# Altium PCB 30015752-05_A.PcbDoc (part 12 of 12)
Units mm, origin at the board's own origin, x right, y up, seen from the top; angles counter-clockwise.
Board outline 100.05 x 72 mm, 10 copper layers (Top, GND_2, Signal_3, Signal_4, PWR_5, GND_6, Signal_7, Signal_8, GND_9, Bottom), stack 1.493 mm thick; 577 components, 546 nets, 2389 pads, 1412 vias.
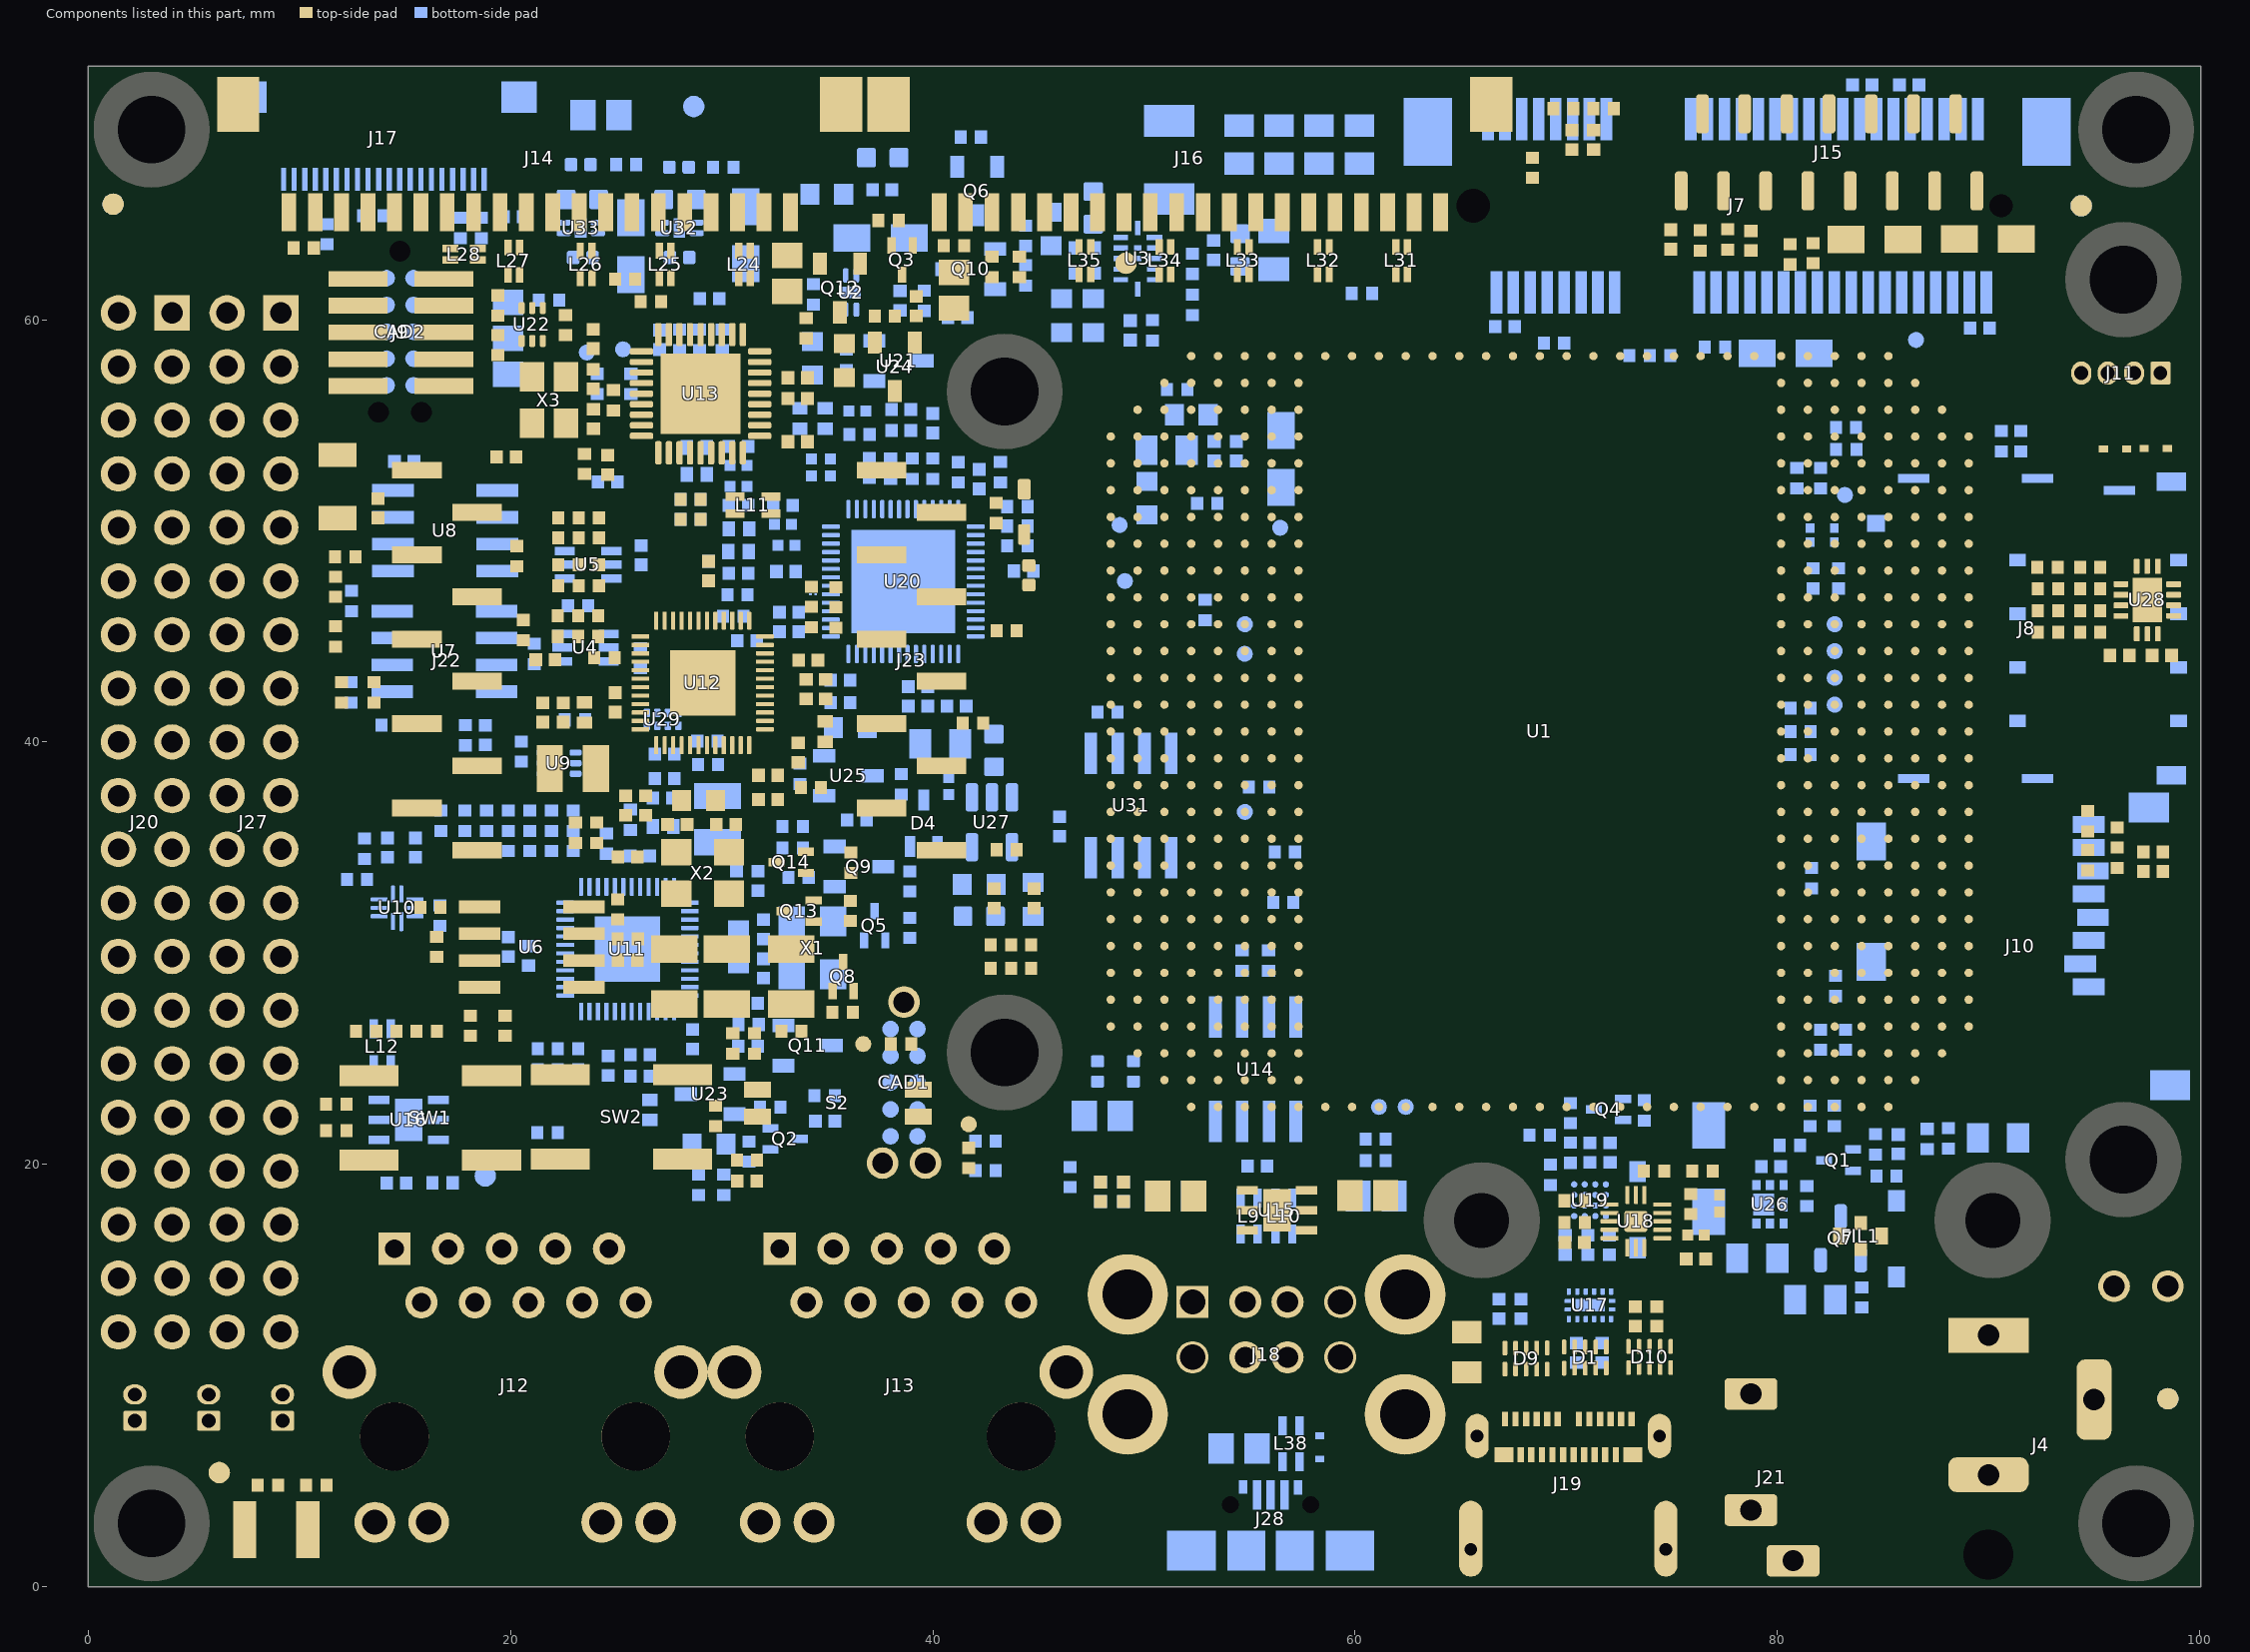
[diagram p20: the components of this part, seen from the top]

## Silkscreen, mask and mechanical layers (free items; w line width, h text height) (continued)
Sheet Graphics:
  drawing of 795 lines, arcs and shapes, not listed
  text "1" at 333.273,124.993 h4.57
  text "4" at -85.192,124.358 h4.57
  text "3" at 57.048,124.358 h4.57
  text "2" at 196.113,123.723 h4.57
  text "D" at -145.517,85.623 h7.11
  text "D" at 399.821,81.178 h7.11
  text "CUT OUT" at 45.695,72.644 h1.25
  text "CUT OUT" at 1.27,72.593 h1.25
  text "CUT OUT" at 153.492,72.593 h1.25
  text "CUT OUT" at 254.356,72.593 h1.25
  text "CUT OUT" at 101.981,63.754 h1.25 r90
  text "CUT OUT" at 204.394,63.703 h1.25 r90
  text "CUT OUT" at 306.908,63.043 h1.25 r90
  text "CUT OUT" at 71,39.5 h1.5
  text "CUT OUT" at 204.445,31.521 h1.25 r90
  text "CUT OUT" at -0.66,30.734 h1.25 r90
  text "CUT OUT" at 306.934,28.245 h1.25 r90
  text "CUT OUT" at 101.981,27.584 h1.25 r90
  text "CUT OUT" at 25.248,-2.616 h1.5
  text "CUT OUT" at 107.823,-2.718 h1.5
  text "CUT OUT" at 213.639,-2.896 h1.5
  text "CUT OUT" at 286.233,-2.896 h1.5
  text "C" at -145.517,-23.597 h7.11
  text "C" at 398.551,-23.597 h7.11
  text "1. Manufacture in accordance with IPC-6012, class 2. Inspect to IPC-A-600, class 2." at 185,-30 h6
  text "T" at -119.157,-40.532 h6.06
  text "a" at -116.729,-40.532 h6.06
  text "r" at -114.3,-40.532 h6.06
  text "g" at -112.565,-40.532 h6.06
  text "e" at -110.137,-40.532 h6.06
  text "t" at -107.361,-40.532 h6.06
  text "T" at -95.04,-40.532 h6.06
  text "o" at -92.611,-40.532 h6.06
  text "l" at -89.836,-40.532 h6.06
  text "+" at -87.407,-40.532 h6.06
  text "/" at -84.978,-40.532 h6.06
  text "-" at -82.897,-40.532 h6.06
  text "%" at -81.162,-40.532 h6.06
  text "L" at -72.696,-40.532 h6.06
  text "a" at -70.614,-40.532 h6.06
  text "y" at -68.186,-40.532 h6.06
  text "e" at -65.757,-40.532 h6.06
  text "r" at -62.981,-40.532 h6.06
  text "N" at -60.206,-40.532 h6.06
  text "o" at -56.736,-40.532 h6.06
  text "." at -53.961,-40.532 h6.06
  text "R" at -46.806,-40.532 h6.06
  text "e" at -44.03,-40.532 h6.06
  text "f" at -41.254,-40.532 h6.06
  text "e" at -39.519,-40.532 h6.06
  text "r" at -36.744,-40.532 h6.06
  text "e" at -35.009,-40.532 h6.06
  text "n" at -32.233,-40.532 h6.06
  text "c" at -29.458,-40.532 h6.06
  text "e" at -27.376,-40.532 h6.06
  text "T" at -20.915,-40.532 h6.06
  text "r" at -18.486,-40.532 h6.06
  text "a" at -16.751,-40.532 h6.06
  text "c" at -14.323,-40.532 h6.06
  text "e" at -12.241,-40.532 h6.06
  text "S" at -8.425,-40.532 h6.06
  text "p" at -5.996,-40.532 h6.06
  text "a" at -3.22,-40.532 h6.06
  text "c" at -0.792,-40.532 h6.06
  text "i" at 1.29,-40.532 h6.06
  text "n" at 2.678,-40.532 h6.06
  text "g" at 5.454,-40.532 h6.06
  text "S" at 8.923,-40.532 h6.06
  text "1" at 11.352,-40.532 h6.06
  text "T" at 17.389,-40.532 h6.06
  text "r" at 19.818,-40.532 h6.06
  text "a" at 21.552,-40.532 h6.06
  text "c" at 23.981,-40.532 h6.06
  text "e" at 26.063,-40.532 h6.06
  text "W" at 29.879,-40.532 h6.06
  text "i" at 34.737,-40.532 h6.06
  text "d" at 36.124,-40.532 h6.06
  text "t" at 38.9,-40.532 h6.06
  text "h" at 40.635,-40.532 h6.06
  text "W" at 44.451,-40.532 h6.06
  text "1" at 49.309,-40.532 h6.06
  text "2. Manufacturing process and materials used must comply with ROHS directive / 2002/95/EC." at 185,-45 h6
  text "I" at -124.477,-47.471 h6.06
  text "m" at -123.09,-47.471 h6.06
  text "p" at -118.926,-47.471 h6.06
  text "e" at -116.15,-47.471 h6.06
  text "d" at -113.375,-47.471 h6.06
  text "a" at -110.599,-47.471 h6.06
  text "n" at -108.171,-47.471 h6.06
  text "c" at -105.395,-47.471 h6.06
  text "e" at -103.313,-47.471 h6.06
  text "L" at -43.968,-47.471 h6.06
  text "a" at -41.886,-47.471 h6.06
  text "y" at -39.458,-47.471 h6.06
  text "e" at -37.029,-47.471 h6.06
  text "r" at -34.254,-47.471 h6.06
  text "(" at -32.519,-47.471 h6.06
  text "s" at -30.784,-47.471 h6.06
  text ")" at -28.702,-47.471 h6.06
  text "(" at -8.856,-47.471 h6.06
  text "M" at -7.122,-47.471 h6.06
  text "I" at -2.611,-47.471 h6.06
  text "L" at -1.223,-47.471 h6.06
  text ")" at 0.858,-47.471 h6.06
  text "(" at 29.093,-47.471 h6.06
  text "M" at 30.828,-47.471 h6.06
  text "I" at 35.338,-47.471 h6.06
  text "L" at 36.726,-47.471 h6.06
  text ")" at 38.808,-47.471 h6.06
  text "5" at -123.413,-54.757 h6.06
  text "0" at -120.985,-54.757 h6.06
  text "o" at -118.556,-54.757 h6.06
  text "h" at -115.78,-54.757 h6.06
  text "m" at -113.005,-54.757 h6.06
  text "_" at -108.841,-54.757 h6.06
  text "S" at -106.413,-54.757 h6.06
  text "E" at -103.984,-54.757 h6.06
  text "1" at -88.301,-54.757 h6.06
  text "0" at -85.873,-54.757 h6.06
  text "1" at -63.475,-54.757 h6.06
  text "2" at -36.52,-54.757 h6.06
  text "N" at -7.438,-54.757 h6.06
  text "/" at -3.968,-54.757 h6.06
  text "A" at -1.886,-54.757 h6.06
  text "5" at 33.704,-54.757 h6.06
  text "5" at -123.413,-61.696 h6.06
  text "0" at -120.985,-61.696 h6.06
  text "o" at -118.556,-61.696 h6.06
  text "h" at -115.78,-61.696 h6.06
  text "m" at -113.005,-61.696 h6.06
  text "_" at -108.841,-61.696 h6.06
  text "S" at -106.413,-61.696 h6.06
  text "E" at -103.984,-61.696 h6.06
  text "1" at -88.301,-61.696 h6.06
  text "0" at -85.873,-61.696 h6.06
  text "3" at -63.475,-61.696 h6.06
  text "2" at -39.358,-61.696 h6.06
  text "&" at -36.929,-61.696 h6.06
  text "5" at -33.459,-61.696 h6.06
  text "N" at -7.438,-61.696 h6.06
  text "/" at -3.968,-61.696 h6.06
  text "A" at -1.886,-61.696 h6.06
  text "5" at 31.93,-61.696 h6.06
  text "." at 34.359,-61.696 h6.06
  text "6" at 35.747,-61.696 h6.06
  text "3. MATERIAL: ITEQ IT-180A /     Material should comply with IPC-4104/99/101/126 /     See Stack-up for details." at 185,-65 h6
  text "5" at -123.413,-68.635 h6.06
  text "0" at -120.985,-68.635 h6.06
  text "o" at -118.556,-68.635 h6.06
  text "h" at -115.78,-68.635 h6.06
  text "m" at -113.005,-68.635 h6.06
  text "_" at -108.841,-68.635 h6.06
  text "S" at -106.413,-68.635 h6.06
  text "E" at -103.984,-68.635 h6.06
  text "1" at -88.301,-68.635 h6.06
  text "0" at -85.873,-68.635 h6.06
  text "4" at -63.475,-68.635 h6.06
  text "2" at -39.358,-68.635 h6.06
  text "&" at -36.929,-68.635 h6.06
  text "5" at -33.459,-68.635 h6.06
  text "N" at -7.438,-68.635 h6.06
  text "/" at -3.968,-68.635 h6.06
  text "A" at -1.886,-68.635 h6.06
  text "5" at 31.93,-68.635 h6.06
  text "." at 34.359,-68.635 h6.06
  text "6" at 35.747,-68.635 h6.06
  text "4. SURFACE FINISH: Apply ENIG to all exposed copper per IPC-4552." at 185,-72.5 h6
  text "5" at -123.413,-75.574 h6.06
  text "0" at -120.985,-75.574 h6.06
  text "o" at -118.556,-75.574 h6.06
  text "h" at -115.78,-75.574 h6.06
  text "m" at -113.005,-75.574 h6.06
  text "_" at -108.841,-75.574 h6.06
  text "S" at -106.413,-75.574 h6.06
  text "E" at -103.984,-75.574 h6.06
  text "1" at -88.301,-75.574 h6.06
  text "0" at -85.873,-75.574 h6.06
  text "7" at -63.475,-75.574 h6.06
  text "6" at -39.358,-75.574 h6.06
  text "&" at -36.929,-75.574 h6.06
  text "9" at -33.459,-75.574 h6.06
  text "N" at -7.438,-75.574 h6.06
  text "/" at -3.968,-75.574 h6.06
  text "A" at -1.886,-75.574 h6.06
  text "5" at 31.93,-75.574 h6.06
  text "." at 34.359,-75.574 h6.06
  text "6" at 35.747,-75.574 h6.06
  text "5. Starting copper weight is 1/2oz. on all layers" at 185,-80 h6
  text "5" at -123.413,-82.513 h6.06
  text "0" at -120.985,-82.513 h6.06
  text "o" at -118.556,-82.513 h6.06
  text "h" at -115.78,-82.513 h6.06
  text "m" at -113.005,-82.513 h6.06
  text "_" at -108.841,-82.513 h6.06
  text "S" at -106.413,-82.513 h6.06
  text "E" at -103.984,-82.513 h6.06
  text "1" at -88.301,-82.513 h6.06
  text "0" at -85.873,-82.513 h6.06
  text "8" at -63.475,-82.513 h6.06
  text "6" at -39.358,-82.513 h6.06
  text "&" at -36.929,-82.513 h6.06
  text "9" at -33.459,-82.513 h6.06
  text "N" at -7.438,-82.513 h6.06
  text "/" at -3.968,-82.513 h6.06
  text "A" at -1.886,-82.513 h6.06
  text "5" at 31.93,-82.513 h6.06
  text "." at 34.359,-82.513 h6.06
  text "6" at 35.747,-82.513 h6.06
  text "5" at -123.413,-89.452 h6.06
  text "0" at -120.985,-89.452 h6.06
  text "o" at -118.556,-89.452 h6.06
  text "h" at -115.78,-89.452 h6.06
  text "m" at -113.005,-89.452 h6.06
  text "_" at -108.841,-89.452 h6.06
  text "S" at -106.413,-89.452 h6.06
  text "E" at -103.984,-89.452 h6.06
  text "1" at -88.301,-89.452 h6.06
  text "0" at -85.873,-89.452 h6.06
  text "1" at -64.539,-89.452 h6.06
  text "0" at -62.11,-89.452 h6.06
  text "9" at -36.52,-89.452 h6.06
  text "N" at -7.438,-89.452 h6.06
  text "/" at -3.968,-89.452 h6.06
  text "A" at -1.886,-89.452 h6.06
  text "5" at 33.704,-89.452 h6.06
  text "6. SOLDER MASK: LPI over bare copper. / SOLDER MASK COLOR: BLUE" at 185,-95 h6
  text "8" at -125.541,-96.391 h6.06
  text "5" at -123.113,-96.391 h6.06
  text "o" at -120.684,-96.391 h6.06
  text "h" at -117.908,-96.391 h6.06
  text "m" at -115.133,-96.391 h6.06
  text "_" at -110.969,-96.391 h6.06
  text "D" at -108.541,-96.391 h6.06
  text "I" at -105.418,-96.391 h6.06
  text "F" at -104.03,-96.391 h6.06
  text "F" at -101.602,-96.391 h6.06
  text "1" at -88.301,-96.391 h6.06
  text "0" at -85.873,-96.391 h6.06
  text "1" at -63.475,-96.391 h6.06
  text "2" at -36.52,-96.391 h6.06
  text "8" at -6.374,-96.391 h6.06
  text "." at -3.945,-96.391 h6.06
  text "6" at -2.557,-96.391 h6.06
  text "5" at 31.93,-96.391 h6.06
  text "." at 34.359,-96.391 h6.06
  text "9" at 35.747,-96.391 h6.06
  text "8" at -125.541,-103.33 h6.06
  text "5" at -123.113,-103.33 h6.06
  text "o" at -120.684,-103.33 h6.06
  text "h" at -117.908,-103.33 h6.06
  text "m" at -115.133,-103.33 h6.06
  text "_" at -110.969,-103.33 h6.06
  text "D" at -108.541,-103.33 h6.06
  text "I" at -105.418,-103.33 h6.06
  text "F" at -104.03,-103.33 h6.06
  text "F" at -101.602,-103.33 h6.06
  text "1" at -88.301,-103.33 h6.06
  text "0" at -85.873,-103.33 h6.06
  text "3" at -63.475,-103.33 h6.06
  text "2" at -39.358,-103.33 h6.06
  text "&" at -36.929,-103.33 h6.06
  text "5" at -33.459,-103.33 h6.06
  text "7" at -6.374,-103.33 h6.06
  text "." at -3.945,-103.33 h6.06
  text "6" at -2.557,-103.33 h6.06
  text "6" at 31.93,-103.33 h6.06
  text "." at 34.359,-103.33 h6.06
  text "9" at 35.747,-103.33 h6.06
  text "8" at -125.541,-110.269 h6.06
  text "5" at -123.113,-110.269 h6.06
  text "o" at -120.684,-110.269 h6.06
  text "h" at -117.908,-110.269 h6.06
  text "m" at -115.133,-110.269 h6.06
  text "_" at -110.969,-110.269 h6.06
  text "D" at -108.541,-110.269 h6.06
  text "I" at -105.418,-110.269 h6.06
  text "F" at -104.03,-110.269 h6.06
  text "F" at -101.602,-110.269 h6.06
  text "1" at -88.301,-110.269 h6.06
  text "0" at -85.873,-110.269 h6.06
  text "1" at -64.539,-110.269 h6.06
  text "0" at -62.11,-110.269 h6.06
  text "9" at -36.52,-110.269 h6.06
  text "8" at -6.374,-110.269 h6.06
  text "." at -3.945,-110.269 h6.06
  text "6" at -2.557,-110.269 h6.06
  text "5" at 31.93,-110.269 h6.06
  text "." at 34.359,-110.269 h6.06
  text "9" at 35.747,-110.269 h6.06
  text "9" at -125.541,-117.208 h6.06
  text "0" at -123.113,-117.208 h6.06
  text "o" at -120.684,-117.208 h6.06
  text "h" at -117.908,-117.208 h6.06
  text "m" at -115.133,-117.208 h6.06
  text "_" at -110.969,-117.208 h6.06
  text "D" at -108.541,-117.208 h6.06
  text "I" at -105.418,-117.208 h6.06
  text "F" at -104.03,-117.208 h6.06
  text "F" at -101.602,-117.208 h6.06
  text "1" at -88.301,-117.208 h6.06
  text "0" at -85.873,-117.208 h6.06
  text "1" at -63.475,-117.208 h6.06
  text "2" at -36.52,-117.208 h6.06
  text "9" at -6.374,-117.208 h6.06
  text "." at -3.945,-117.208 h6.06
  text "3" at -2.557,-117.208 h6.06
  text "5" at 31.93,-117.208 h6.06
  text "." at 34.359,-117.208 h6.06
  text "2" at 35.747,-117.208 h6.06
  text "7. SILKSCREEN: Apply on top and bottom sides of PCB. / SILKSCREEN COLOR: WHITE" at 185,-117.5 h6
  text "9" at -125.541,-124.148 h6.06
  text "0" at -123.113,-124.148 h6.06
  text "o" at -120.684,-124.148 h6.06
  text "h" at -117.908,-124.148 h6.06
  text "m" at -115.133,-124.148 h6.06
  text "_" at -110.969,-124.148 h6.06
  text "D" at -108.541,-124.148 h6.06
  text "I" at -105.418,-124.148 h6.06
  text "F" at -104.03,-124.148 h6.06
  text "F" at -101.602,-124.148 h6.06
  text "1" at -88.301,-124.148 h6.06
  text "0" at -85.873,-124.148 h6.06
  text "3" at -63.475,-124.148 h6.06
  text "2" at -39.358,-124.148 h6.06
  text "&" at -36.929,-124.148 h6.06
  text "5" at -33.459,-124.148 h6.06
  text "8" at -6.374,-124.148 h6.06
  text "." at -3.945,-124.148 h6.06
  text "3" at -2.557,-124.148 h6.06
  text "6" at 31.93,-124.148 h6.06
  text "." at 34.359,-124.148 h6.06
  text "2" at 35.747,-124.148 h6.06
  text "B" at -145.517,-129.642 h7.11
  text "B" at 398.551,-129.642 h7.11
  text "9" at -125.541,-131.087 h6.06
  text "0" at -123.113,-131.087 h6.06
  text "o" at -120.684,-131.087 h6.06
  text "h" at -117.908,-131.087 h6.06
  text "m" at -115.133,-131.087 h6.06
  text "_" at -110.969,-131.087 h6.06
  text "D" at -108.541,-131.087 h6.06
  text "I" at -105.418,-131.087 h6.06
  text "F" at -104.03,-131.087 h6.06
  text "F" at -101.602,-131.087 h6.06
  text "1" at -88.301,-131.087 h6.06
  text "0" at -85.873,-131.087 h6.06
  text "4" at -63.475,-131.087 h6.06
  text "2" at -39.358,-131.087 h6.06
  text "&" at -36.929,-131.087 h6.06
  text "5" at -33.459,-131.087 h6.06
  text "8" at -6.374,-131.087 h6.06
  text "." at -3.945,-131.087 h6.06
  text "3" at -2.557,-131.087 h6.06
  text "6" at 31.93,-131.087 h6.06
  text "." at 34.359,-131.087 h6.06
  text "2" at 35.747,-131.087 h6.06
  text "8. GERBER FILE FORMAT: 274-X WITH 4/3 accuracy (XXXX.XXX). / Gerber and drill in mm." at 185,-132.5 h6
  text "9" at -125.541,-138.026 h6.06
  text "0" at -123.113,-138.026 h6.06
  text "o" at -120.684,-138.026 h6.06
  text "h" at -117.908,-138.026 h6.06
  text "m" at -115.133,-138.026 h6.06
  text "_" at -110.969,-138.026 h6.06
  text "D" at -108.541,-138.026 h6.06
  text "I" at -105.418,-138.026 h6.06
  text "F" at -104.03,-138.026 h6.06
  text "F" at -101.602,-138.026 h6.06
  text "1" at -88.301,-138.026 h6.06
  text "0" at -85.873,-138.026 h6.06
  text "8" at -63.475,-138.026 h6.06
  text "6" at -39.358,-138.026 h6.06
  text "&" at -36.929,-138.026 h6.06
  text "9" at -33.459,-138.026 h6.06
  text "8" at -6.374,-138.026 h6.06
  text "." at -3.945,-138.026 h6.06
  text "3" at -2.557,-138.026 h6.06
  text "6" at 31.93,-138.026 h6.06
  text "." at 34.359,-138.026 h6.06
  text "2" at 35.747,-138.026 h6.06
  text "9. Maximum warp and twist per IPC-6012 of 0.75% inch/inch." at 185,-142.5 h6
  text "9" at -125.541,-144.965 h6.06
  text "0" at -123.113,-144.965 h6.06
  text "o" at -120.684,-144.965 h6.06
  text "h" at -117.908,-144.965 h6.06
  text "m" at -115.133,-144.965 h6.06
  text "_" at -110.969,-144.965 h6.06
  text "D" at -108.541,-144.965 h6.06
  text "I" at -105.418,-144.965 h6.06
  text "F" at -104.03,-144.965 h6.06
  text "F" at -101.602,-144.965 h6.06
  text "1" at -88.301,-144.965 h6.06
  text "0" at -85.873,-144.965 h6.06
  text "1" at -64.539,-144.965 h6.06
  text "0" at -62.11,-144.965 h6.06
  text "9" at -36.52,-144.965 h6.06
  text "9" at -6.374,-144.965 h6.06
  text "." at -3.945,-144.965 h6.06
  text "3" at -2.557,-144.965 h6.06
  text "5" at 31.93,-144.965 h6.06
  text "." at 34.359,-144.965 h6.06
  text "2" at 35.747,-144.965 h6.06
  text "1" at -126.96,-151.904 h6.06
  text "0" at -124.531,-151.904 h6.06
  text "0" at -122.103,-151.904 h6.06
  text "o" at -119.674,-151.904 h6.06
  text "h" at -116.898,-151.904 h6.06
  text "m" at -114.123,-151.904 h6.06
  text "_" at -109.959,-151.904 h6.06
  text "D" at -107.531,-151.904 h6.06
  text "I" at -104.408,-151.904 h6.06
  text "F" at -103.02,-151.904 h6.06
  text "F" at -100.592,-151.904 h6.06
  text "1" at -88.301,-151.904 h6.06
  text "0" at -85.873,-151.904 h6.06
  text "1" at -63.475,-151.904 h6.06
  text "2" at -36.52,-151.904 h6.06
  text "9" at -4.246,-151.904 h6.06
  text "4" at 33.704,-151.904 h6.06
  text "1" at -126.96,-158.843 h6.06
  text "0" at -124.531,-158.843 h6.06
  text "0" at -122.103,-158.843 h6.06
  text "o" at -119.674,-158.843 h6.06
  text "h" at -116.898,-158.843 h6.06
  text "m" at -114.123,-158.843 h6.06
  text "_" at -109.959,-158.843 h6.06
  text "D" at -107.531,-158.843 h6.06
  text "I" at -104.408,-158.843 h6.06
  text "F" at -103.02,-158.843 h6.06
  text "F" at -100.592,-158.843 h6.06
  text "1" at -88.301,-158.843 h6.06
  text "0" at -85.873,-158.843 h6.06
  text "3" at -63.475,-158.843 h6.06
  text "2" at -39.358,-158.843 h6.06
  text "&" at -36.929,-158.843 h6.06
  text "5" at -33.459,-158.843 h6.06
  text "8" at -6.374,-158.843 h6.06
  text "." at -3.945,-158.843 h6.06
  text "1" at -2.557,-158.843 h6.06
  text "4" at 31.93,-158.843 h6.06
  text "." at 34.359,-158.843 h6.06
  text "9" at 35.747,-158.843 h6.06
  text "10. Copper thieving is NOT allowed within board outline. / Thieving may be placed in array rails." at 185,-160 h6
  text "1" at -126.96,-165.782 h6.06
  text "0" at -124.531,-165.782 h6.06
  text "0" at -122.103,-165.782 h6.06
  text "o" at -119.674,-165.782 h6.06
  text "h" at -116.898,-165.782 h6.06
  text "m" at -114.123,-165.782 h6.06
  text "_" at -109.959,-165.782 h6.06
  text "D" at -107.531,-165.782 h6.06
  text "I" at -104.408,-165.782 h6.06
  text "F" at -103.02,-165.782 h6.06
  text "F" at -100.592,-165.782 h6.06
  text "1" at -88.301,-165.782 h6.06
  text "0" at -85.873,-165.782 h6.06
  text "1" at -64.539,-165.782 h6.06
  text "0" at -62.11,-165.782 h6.06
  text "9" at -36.52,-165.782 h6.06
  text "9" at -4.246,-165.782 h6.06
  text "4" at 33.704,-165.782 h6.06
  text "Layer" at -127.263,-176.175 h2
  text "Name" at -113.758,-176.175 h2
  text "Material" at -82.925,-176.175 h2
  text "Thickness" at -60.423,-176.175 h2
  text "Constant" at -38.92,-176.175 h2
  text "Board Layer Stack" at -20.084,-176.175 h2
  text "1" at -127.263,-180.175 h2
  text "Top Overlay" at -113.758,-180.175 h2
  text "11. Plated holes are specified as finished hole sizes (see table). / Plated hole tolerance ±0.003\" (±76µm) / NPTH tolerance ±0.0015\" (±38.1µm)" at 185,-182.5 h6
  text "2" at -127.263,-184.175 h2
  text "Top Solder" at -113.758,-184.175 h2
  text "Dielectric" at -82.925,-184.175 h2
  text "0.70mil" at -60.423,-184.175 h2
  text "0" at -38.92,-184.175 h2
  text "3" at -127.263,-188.175 h2
  text "Top" at -113.758,-188.175 h2
  text "Copper" at -82.925,-188.175 h2
  text "2.04mil" at -60.423,-188.175 h2
  text "12. Slot/Cut-Out tolerance ±0.005\" (±127µm)" at 185,-190 h6
  text "4" at -127.263,-192.175 h2
  text "Dielectric1" at -113.758,-192.175 h2
  text "2313" at -82.925,-192.175 h2
  text "3.81mil" at -60.423,-192.175 h2
  text "4.3" at -38.92,-192.175 h2
  text "5" at -127.263,-196.175 h2
  text "GND_2" at -113.758,-196.175 h2
  text "Copper" at -82.925,-196.175 h2
  text "0.50mil" at -60.423,-196.175 h2
  text "13. See table for controlled impedance trace widths." at 185,-200 h6
  text "6" at -127.263,-200.175 h2
  text "Dielectric2" at -113.758,-200.175 h2
  text "CORE" at -82.925,-200.175 h2
  text "5.00mil" at -60.423,-200.175 h2
  text "4.15" at -38.92,-200.175 h2
  text "7" at -127.263,-204.175 h2
  text "Signal_3" at -113.758,-204.175 h2
  text "Copper" at -82.925,-204.175 h2
  text "0.50mil" at -60.423,-204.175 h2
  text "14. Finished thickness is 0.062\" ±0.006\" (1.52 ± 152µm)" at 185,-207.5 h6
  text "8" at -127.263,-208.175 h2
  text "Dielectric3" at -113.758,-208.175 h2
  text "2116H" at -82.925,-208.175 h2
  text "4.42mil" at -60.423,-208.175 h2
  text "4.2" at -38.92,-208.175 h2
  text "9" at -127.263,-212.175 h2
  text "Signal_4" at -113.758,-212.175 h2
  text "Copper" at -82.925,-212.175 h2
  text "0.50mil" at -60.423,-212.175 h2
  text "15. Net Tie NT1 is connected to GND in the design." at 185.1,-214.5 h6
  text "10" at -127.263,-216.175 h2
  text "Dielectric 13" at -113.758,-216.175 h2
  text "CORE" at -82.925,-216.175 h2
  text "5.00mil" at -60.423,-216.175 h2
  text "4.15" at -38.92,-216.175 h2
  text "11" at -127.263,-220.175 h2
  text "PWR_5" at -113.758,-220.175 h2
  text "Copper" at -82.925,-220.175 h2
  text "0.50mil" at -60.423,-220.175 h2
  text "A" at -145.085,-222.352 h7.11
  text "A" at 398.983,-222.352 h7.11
  text "12" at -127.263,-224.175 h2
  text "Dielectric6" at -113.758,-224.175 h2
  text "7628 x 2" at -82.925,-224.175 h2
  text "14.22mil" at -60.423,-224.175 h2
  text "4.6" at -38.92,-224.175 h2
  text "CAD GENERATED:" at 337.718,-227.432 h1.27
  text "CAD GENERATED:" at 337.718,-227.432 h1.27
  text ".pcb_File_Name_No_Path" at 353.212,-227.432 h2.17
  text "13" at -127.263,-228.175 h2
  text "GND_6" at -113.758,-228.175 h2
  text "Copper" at -82.925,-228.175 h2
  text "0.50mil" at -60.423,-228.175 h2
  text "EXCEPT AS MAY BE OTHERWISE PROVIDED BY" at 238.658,-231.496 h2.17
  text "14" at -127.263,-232.175 h2
  text "Dielectric9" at -113.758,-232.175 h2
  text "CORE" at -82.925,-232.175 h2
  text "5.00mil" at -60.423,-232.175 h2
  text "4.15" at -38.92,-232.175 h2
  text "DIGI INTERNATIONAL INC" at 332.638,-233.02 h2.54
  text "CONTRACT, THIS DOCUMENT IS THE PROPERTY" at 238.658,-233.528 h2.17
  text "OF DIGI INTERNATIONAL.  IF RELEASED TO OTHER" at 238.658,-235.56 h2.17
  text "15" at -127.263,-236.175 h2
  text "Signal_7" at -113.758,-236.175 h2
  text "Copper" at -82.925,-236.175 h2
  text "0.50mil" at -60.423,-236.175 h2
  text "9350 Excelsior Blvd Suite 700" at 332.638,-236.576 h2.54
  text "SOURCES, IT SHALL BE RECEIVED BY SUCH" at 238.658,-237.592 h2.17
  text "SOURCES IN TOTAL CONFIDENCE AND SHALL NOT" at 238.658,-239.624 h2.17
  text "Hopkins, MN 55343" at 333.146,-240.132 h2.54
  text "16" at -127.263,-240.175 h2
  text "Dielectric10" at -113.758,-240.175 h2
  text "2116H" at -82.925,-240.175 h2
  text "4.42mil" at -60.423,-240.175 h2
  text "4.2" at -38.92,-240.175 h2
  text "BE RELEASED TO ANY THIRD PARTY OR PARTIES," at 238.658,-241.656 h2.17
  text "NOR USED FOR MANUFACTURE OR SALE OF THE" at 238.658,-243.688 h2.17
  text "17" at -127.263,-244.175 h2
  text "Signal_8" at -113.758,-244.175 h2
  text "Copper" at -82.925,-244.175 h2
  text "0.50mil" at -60.423,-244.175 h2
  text "ARTICLES WITHOUT PRIOR WRITTEN" at 238.658,-245.72 h2.17
  text "DIGI INTERNATIONAL" at 321.75,-246.125 h2.54
  text "AUTHORIZATION." at 238.658,-247.752 h2.17
  text "18" at -127.263,-248.175 h2
  text "Dielectric 12" at -113.758,-248.175 h2
  text "CORE" at -82.925,-248.175 h2
  text "5.00mil" at -60.423,-248.175 h2
  text "4.15" at -38.92,-248.175 h2
  text "ConnectCore 8X" at 323.596,-250.444 h2.54
  text "19" at -127.263,-252.175 h2
  text "GND_9" at -113.758,-252.175 h2
  text "Copper" at -82.925,-252.175 h2
  text "0.50mil" at -60.423,-252.175 h2
  text "ENGINEER" at 238.15,-254.356 h1.27
  text "SINGLE BOARD COMPUTER (SBC)" at 311.45,-254.475 h2.54
  text "SEBASTIEN MEYER" at 255.524,-255.016 h1.27
  text "20" at -127.263,-256.175 h2
  text "Dielectric11" at -113.758,-256.175 h2
  text "2313" at -82.925,-256.175 h2
  text "3.81mil" at -60.423,-256.175 h2
  text "4.3" at -38.92,-256.175 h2
  text "PCB DESIGNER" at 238.15,-259.436 h1.27
  text "SIZE" at 291.49,-259.436 h1.27
  text "CAGE NO." at 299.618,-259.436 h1.27
  text "PCB NO." at 327.558,-259.436 h1.27
  text "REV." at 389.534,-259.436 h1.27
  text "JOSH FLAGSTAD" at 255.524,-260.096 h1.27
  text "21" at -127.263,-260.175 h2
  text "Bottom" at -113.758,-260.175 h2
  text "Copper" at -82.925,-260.175 h2
  text "2.04mil" at -60.423,-260.175 h2
  text "30015752-05" at 343.5,-263.5 h2.54
  text "DATE" at 238.15,-264.008 h1.27
  text "C" at 291.998,-264.008 h2.54
  text "A" at 389.534,-264.008 h2.54
  text "22" at -127.263,-264.175 h2
  text "Bottom Solder" at -113.758,-264.175 h2
  text "Dielectric" at -82.925,-264.175 h2
  text "0.70mil" at -60.423,-264.175 h2
  text "0" at -38.92,-264.175 h2
  text ".Print_Date" at 254.914,-265.024 h1.27
  text "23" at -127.263,-268.175 h2
  text "Bottom Overlay" at -113.758,-268.175 h2
  text "JIRA EPIC:" at 238.15,-269.088 h1.27
  text ".Print_Scale" at 289.458,-270.612 h1.27
  text "SVN HEAD REV:" at 314.858,-270.612 h1.27
  text ".VersionControl_RevNumber" at 330.606,-270.612 h1.27
  text "SHEET:" at 352.958,-270.612 h1.27
  text "1 OF 1" at 371.5,-270.612 h1.27
  text "1" at 333.273,-280.137 h4.57
  text "4" at -85.192,-280.772 h4.57
  text "3" at 57.048,-280.772 h4.57
  text "2" at 196.113,-281.407 h4.57
Drill Drawing:
  lines w0.1: 28.262,-259.2 175.401,-259.2 ; 28.262,-176.7 175.401,-176.7 ; 41.554,-262.95 41.554,-172.95 ; 57.5,-262.95 57.5,-172.95 ; 85.942,-262.95 85.942,-172.95 ; 114.383,-262.95 114.383,-172.95 ; 144.244,-262.95 144.244,-172.95 ; 156.411,-262.95 156.411,-172.95 ; 28.262,-262.95 175.401,-262.95 175.401,-172.95 28.262,-172.95 28.262,-262.95 ; 29.71,-212.658 30.127,-212.658 30.544,-213.075 30.96,-212.658 31.377,-212.658 30.96,-212.242 31.377,-211.825 30.96,-211.825 30.544,-211.408 30.127,-211.825 29.71,-211.825 30.127,-212.242 29.71,-212.658 ; 29.71,-201.825 31.377,-201.825 31.377,-200.158 29.71,-200.158 29.71,-201.825 ; 29.71,-198.075 30.544,-197.658 31.377,-198.075 30.96,-197.242 31.377,-196.408 30.544,-196.825 29.71,-196.408 30.127,-197.242 29.71,-198.075 ; 29.71,-181.408 31.377,-181.408 30.544,-183.075 29.71,-181.408 ; 29.71,-179.325 31.377,-179.325 31.377,-177.658 29.71,-177.658 29.71,-179.325 ; 30.044,-212.492 30.294,-212.492 30.544,-212.742 30.794,-212.492 31.044,-212.492 30.794,-212.242 31.044,-211.992 30.794,-211.992 30.544,-211.742 30.294,-211.992 30.044,-211.992 30.294,-212.242 30.044,-212.492 ; 30.044,-197.742 30.544,-197.492 31.044,-197.742 30.794,-197.242 31.044,-196.742 30.544,-196.992 30.044,-196.742 30.294,-197.242 30.044,-197.742 ; 30.044,-178.992 31.044,-178.992 31.044,-177.992 30.044,-177.992 30.044,-178.992
  text ".Layer_Name" at 95.4,-152.025 h2.54
  text "Symbol" at 30.512,-175.575 h1.8
  text "Count" at 42.679,-175.575 h1.8
  text "Hole Size" at 58.625,-175.575 h1.8
  text "Hole Length" at 87.067,-175.575 h1.8
  text "Rout Path Length" at 115.508,-175.575 h1.8
  text "Plated" at 145.369,-175.575 h1.8
  text "Hole Type" at 157.536,-175.575 h1.8
  text "1412" at 42.679,-179.325 h1.5
  text "0.200mm (7.87mil)" at 58.625,-179.325 h1.5
  text "-" at 87.067,-179.325 h1.5
  text "-" at 115.508,-179.325 h1.5
  text "PTH" at 145.369,-179.325 h1.5
  text "Round" at 157.536,-179.325 h1.5
  text "10" at 42.679,-183.075 h1.5
  text "0.650mm (25.59mil)" at 58.625,-183.075 h1.5
  text "-" at 87.067,-183.075 h1.5
  text "-" at 115.508,-183.075 h1.5
  text "PTH" at 145.369,-183.075 h1.5
  text "Round" at 157.536,-183.075 h1.5
  text "2" at 42.679,-186.825 h1.5
  text "0.813mm (32.00mil)" at 58.625,-186.825 h1.5
  text "-" at 87.067,-186.825 h1.5
  text "-" at 115.508,-186.825 h1.5
  text "NPTH" at 145.369,-186.825 h1.5
  text "Round" at 157.536,-186.825 h1.5
  text "G" at 29.888,-186.925 h1.67
  text "20" at 42.679,-190.575 h1.5
  text "0.889mm (35.00mil)" at 58.625,-190.575 h1.5
  text "-" at 87.067,-190.575 h1.5
  text "-" at 115.508,-190.575 h1.5
  text "PTH" at 145.369,-190.575 h1.5
  text "Round" at 157.536,-190.575 h1.5
  text "I" at 30.166,-190.675 h1.67
  text "6" at 42.679,-194.325 h1.5
  text "0.991mm (39.00mil)" at 58.625,-194.325 h1.5
  text "-" at 87.067,-194.325 h1.5
  text "-" at 115.508,-194.325 h1.5
  text "NPTH" at 145.369,-194.325 h1.5
  text "Round" at 157.536,-194.325 h1.5
  text "W" at 29.888,-194.425 h1.67
  text "4" at 42.679,-198.075 h1.5
  text "1.000mm (39.37mil)" at 58.625,-198.075 h1.5
  text "-" at 87.067,-198.075 h1.5
  text "-" at 115.508,-198.075 h1.5
  text "PTH" at 145.369,-198.075 h1.5
  text "Round" at 157.536,-198.075 h1.5
  text "80" at 42.679,-201.825 h1.5
  text "1.016mm (40.00mil)" at 58.625,-201.825 h1.5
  text "-" at 87.067,-201.825 h1.5
  text "-" at 115.508,-201.825 h1.5
  text "PTH" at 145.369,-201.825 h1.5
  text "Round" at 157.536,-201.825 h1.5
  text "2" at 42.679,-205.575 h1.5
  text "1.020mm (40.16mil)" at 58.625,-205.575 h1.5
  text "-" at 87.067,-205.575 h1.5
  text "-" at 115.508,-205.575 h1.5
  text "PTH" at 145.369,-205.575 h1.5
  text "Round" at 157.536,-205.575 h1.5
  text "F" at 29.888,-205.675 h1.67
  text "1" at 42.679,-209.325 h1.5
  text "1.100mm (43.31mil)" at 58.625,-209.325 h1.5
  text "-" at 87.067,-209.325 h1.5
  text "-" at 115.508,-209.325 h1.5
  text "NPTH" at 145.369,-209.325 h1.5
  text "Round" at 157.536,-209.325 h1.5
  text "D" at 29.888,-209.425 h1.67
  text "12" at 42.679,-213.075 h1.5
  text "1.200mm (47.24mil)" at 58.625,-213.075 h1.5
  text "-" at 87.067,-213.075 h1.5
  text "-" at 115.508,-213.075 h1.5
  text "PTH" at 145.369,-213.075 h1.5
  text "Round" at 157.536,-213.075 h1.5
  text "1" at 42.679,-216.825 h1.5
  text "1.600mm (62.99mil)" at 58.625,-216.825 h1.5
  text "-" at 87.067,-216.825 h1.5
  text "-" at 115.508,-216.825 h1.5
  text "NPTH" at 145.369,-216.825 h1.5
  text "Round" at 157.536,-216.825 h1.5
  text "C" at 29.888,-216.925 h1.67
  text "4" at 42.679,-220.575 h1.5
  text "1.600mm (63.00mil)" at 58.625,-220.575 h1.5
  text "-" at 87.067,-220.575 h1.5
  text "-" at 115.508,-220.575 h1.5
  text "PTH" at 145.369,-220.575 h1.5
  text "Round" at 157.536,-220.575 h1.5
  text "K" at 29.888,-220.675 h1.67
  text "1" at 42.679,-224.325 h1.5
  text "2.362mm (93.00mil)" at 58.625,-224.325 h1.5
  text "-" at 87.067,-224.325 h1.5
  text "-" at 115.508,-224.325 h1.5
  text "NPTH" at 145.369,-224.325 h1.5
  text "Round" at 157.536,-224.325 h1.5
  text "T" at 29.888,-224.425 h1.67
  text "4" at 42.679,-228.075 h1.5
  text "2.362mm (93.00mil)" at 58.625,-228.075 h1.5
  text "-" at 87.067,-228.075 h1.5
  text "-" at 115.508,-228.075 h1.5
  text "PTH" at 145.369,-228.075 h1.5
  text "Round" at 157.536,-228.075 h1.5
  text "O" at 29.888,-228.175 h1.67
  text "2" at 42.679,-231.825 h1.5
  text "2.600mm (102.36mil)" at 58.625,-231.825 h1.5
  text "-" at 87.067,-231.825 h1.5
  text "-" at 115.508,-231.825 h1.5
  text "PTH" at 145.369,-231.825 h1.5
  text "Round" at 157.536,-231.825 h1.5
  text "M" at 29.888,-231.925 h1.67
  text "4" at 42.679,-235.575 h1.5
  text "3.175mm (125.00mil)" at 58.625,-235.575 h1.5
  text "-" at 87.067,-235.575 h1.5
  text "-" at 115.508,-235.575 h1.5
  text "NPTH" at 145.369,-235.575 h1.5
  text "Round" at 157.536,-235.575 h1.5
  text "N" at 29.888,-235.675 h1.67
  text "8" at 42.679,-239.325 h1.5
  text "3.200mm (125.98mil)" at 58.625,-239.325 h1.5
  text "-" at 87.067,-239.325 h1.5
  text "-" at 115.508,-239.325 h1.5
  text "PTH" at 145.369,-239.325 h1.5
  text "Round" at 157.536,-239.325 h1.5
  text "L" at 29.888,-239.425 h1.67
  text "4" at 42.679,-243.075 h1.5
  text "3.250mm (127.95mil)" at 58.625,-243.075 h1.5
  text "-" at 87.067,-243.075 h1.5
  text "-" at 115.508,-243.075 h1.5
  text "NPTH" at 145.369,-243.075 h1.5
  text "Round" at 157.536,-243.075 h1.5
  text "H" at 29.888,-243.175 h1.67
  text "2" at 42.679,-246.825 h1.5
  text "0.600mm (23.62mil)" at 58.625,-246.825 h1.5
  text "1.600mm (62.99mil)" at 87.067,-246.825 h1.5
  text "1.000mm (39.37mil)" at 115.508,-246.825 h1.5
  text "PTH" at 145.369,-246.825 h1.5
  text "Slot" at 157.536,-246.825 h1.5
  text "B" at 29.888,-246.925 h1.67
  text "2" at 42.679,-250.575 h1.5
  text "0.600mm (23.62mil)" at 58.625,-250.575 h1.5
  text "2.100mm (82.68mil)" at 87.067,-250.575 h1.5
  text "1.500mm (59.06mil)" at 115.508,-250.575 h1.5
  text "PTH" at 145.369,-250.575 h1.5
  text "Slot" at 157.536,-250.575 h1.5
  text "A" at 29.888,-250.675 h1.67
  text "3" at 42.679,-254.325 h1.5
  text "1.000mm (39.37mil)" at 58.625,-254.325 h1.5
  text "2.000mm (78.74mil)" at 87.067,-254.325 h1.5
  text "1.000mm (39.37mil)" at 115.508,-254.325 h1.5
  text "PTH" at 145.369,-254.325 h1.5
  text "Slot" at 157.536,-254.325 h1.5
  text "J" at 29.888,-254.425 h1.67
  text "3" at 42.679,-258.075 h1.5
  text "1.016mm (40.00mil)" at 58.625,-258.075 h1.5
  text "3.200mm (126.00mil)" at 87.067,-258.075 h1.5
  text "2.184mm (86.00mil)" at 115.508,-258.075 h1.5
  text "PTH" at 145.369,-258.075 h1.5
  text "Slot" at 157.536,-258.075 h1.5
  text "S" at 29.888,-258.175 h1.67
  text "1587 Total" at 42.679,-261.825 h1.5
  text "Slot definitions :" at 30.512,-265.149 h1.5
  text "Rout Path Length" at 55.91,-265.149 h1.5
  text "= Calculated from tool start centre position to tool end centre position." at 80.057,-265.149 h1.5
  text "Hole Length" at 55.91,-267.349 h1.5
  text "= Rout Path Length + Tool Size = Slot length as defined in the PCB layout" at 72.81,-267.349 h1.5
TOP SUPPORT:
  circle w0.15: c99,71 r1.27
  circle w0.15: c98,65 r1.27
  circle w0.15: c96,40 r1.27
  circle w0.15: c98,1 r1.27
  circle w0.15: c98,8 r1.27
  circle w0.15: c88,14 r1.27
  circle w0.15: c72,63 r1.27
  circle w0.15: c70,13 r1.27
  circle w0.15: c40,28 r1.27
  circle w0.15: c29,62 r1.27
  circle w0.15: c0,0 r1.27
  circle w0.15: c1.725,70.856 r1.27
BOTTOM SUPPORT:
  circle w0.15: c0,14 r1.27
  circle w0.15: c7,2 r1.27
  circle w0.15: c11,14 r1.27
  circle w0.15: c0,50 r1.27
  circle w0.15: c0,31 r1.27
  circle w0.15: c11,31 r1.27
  circle w0.15: c15,37 r1.27
  circle w0.15: c18,54 r1.27
  circle w0.15: c11,52 r1.27
  circle w0.15: c0,62 r1.27
  circle w0.15: c1,65 r1.27
  circle w0.15: c31,41 r1.27
  circle w0.15: c11,61 r1.27
  circle w0.15: c40,28 r1.27
  circle w0.15: c43,59 r1.27
  circle w0.15: c70,2 r1.27
  circle w0.15: c45,53 r1.27
  circle w0.15: c74,13 r1.27
  circle w0.15: c98,8 r1.27
  circle w0.15: c0,5 r1.27
  circle w0.15: c98,65 r1.27
  circle w0.15: c0,0 r1.27

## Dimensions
305,0 to 306.25,-4 on Sheet Graphics
-15,-11.5 to 0,0 on Sheet Graphics
-15,79.5 to -15,-11.5 on Sheet Graphics
-15,79.5 to 320,79.5 on Sheet Graphics
-15,79.5 to 0,72 on Sheet Graphics
0,72 to 0,0 on Sheet Graphics
202.5,72 to 205,72 on Sheet Graphics
0,72 to 102.5,72 on Sheet Graphics
0,72 to 100,72 on Sheet Graphics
